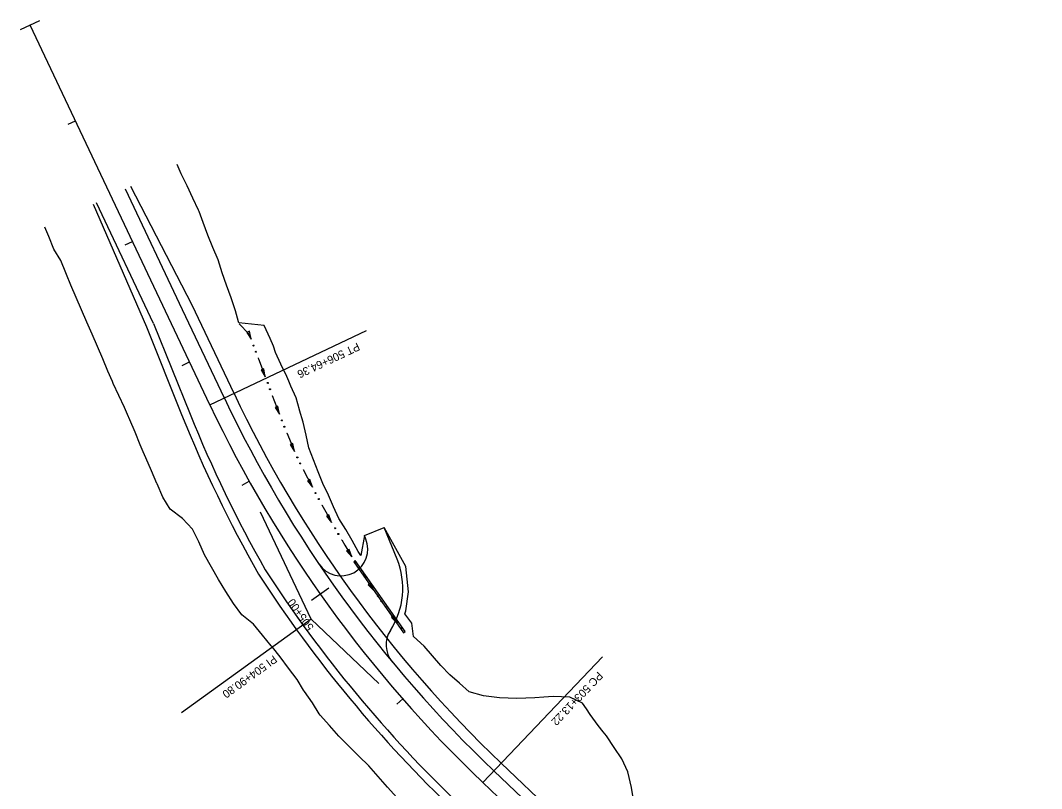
# Model space of a CAD drawing. Extents: x 948761 to 996004, y 1858548 to 1925175.
# Drawn here: x 955106 to 955872, y 1923318 to 1923894 of the extents above; entities that cross this region are included whole.
import ezdxf

# ---------------------------------------------------------------- set-up
doc = ezdxf.new("R2010")
doc.units = 0
for name, color, linetype in [('62', 7, 'Continuous'), ('R_Drainage', 7, 'Continuous'), ('R_Horz Alg', 7, 'Continuous'), ('R_Horz Alg Annot', 7, 'Continuous'), ('R_Proposed Const Limits', 7, 'Continuous'), ('R_Proposed Road', 7, 'Continuous')]:
    doc.layers.add(name, color=color, linetype=linetype)

msp = doc.modelspace()

# ---------------------------------------------------------------- linework, layer by layer
at = {"layer": '62'}
for p, q in [((955278.24, 1923660.85), (955276.27, 1923660.09)), ((955276.27, 1923660.09), (955279.43, 1923654.88)), ((955279.43, 1923654.88), (955278.24, 1923660.85)), ((955289.02, 1923632.8), (955287.04, 1923632.06)), ((955287.04, 1923632.06), (955290.12, 1923626.81)), ((955290.12, 1923626.81), (955289.02, 1923632.8)), ((955299.47, 1923604.65), (955297.49, 1923603.89)), ((955297.49, 1923603.89), (955300.65, 1923598.68)), ((955300.65, 1923598.68), (955299.47, 1923604.65)), ((955310.63, 1923576.81), (955308.68, 1923575.98)), ((955312.01, 1923570.87), (955310.63, 1923576.81)), ((955308.68, 1923575.98), (955312.01, 1923570.87)), ((955323.61, 1923549.82), (955321.73, 1923548.84)), ((955321.73, 1923548.84), (955325.45, 1923544.02)), ((955325.45, 1923544.02), (955323.61, 1923549.82)), ((955337.86, 1923523.42), (955336.02, 1923522.39)), ((955339.86, 1923517.66), (955337.86, 1923523.42)), ((955336.02, 1923522.39), (955339.86, 1923517.66)), ((955352.87, 1923497.44), (955351.05, 1923496.35)), ((955351.05, 1923496.35), (955355.05, 1923491.75)), ((955355.05, 1923491.75), (955352.87, 1923497.44)), ((955368.99, 1923472.18), (955367.25, 1923470.98)), ((955367.25, 1923470.98), (955371.51, 1923466.63)), ((955371.51, 1923466.63), (955368.99, 1923472.18)), ((955386.33, 1923447.7), (955384.63, 1923446.44)), ((955389.05, 1923442.24), (955386.33, 1923447.7)), ((955384.63, 1923446.44), (955389.05, 1923442.24))]:
    msp.add_line(p, q, dxfattribs=at)
for points in [[(955270.43, 1923666.56), (955277.83, 1923659), (955279.43, 1923654.88)], [(955284.86, 1923640.9), (955284.87, 1923640.86)], [(955284.87, 1923640.86), (955285.08, 1923640.31), (955288.59, 1923630.91), (955290.12, 1923626.81)], [(955295.3, 1923612.73), (955295.31, 1923612.71), (955295.32, 1923612.7)], [(955295.32, 1923612.7), (955298.69, 1923603.74), (955300.65, 1923598.68)], [(955306.2, 1923584.74), (955306.22, 1923584.71)], [(955306.22, 1923584.71), (955309.4, 1923577), (955312.01, 1923570.87)], [(955318.55, 1923557.38), (955318.56, 1923557.34)], [(955318.56, 1923557.34), (955321.8, 1923551), (955325.45, 1923544.02)], [(955332.57, 1923530.81), (955332.58, 1923530.78)], [(955332.58, 1923530.78), (955335.44, 1923525.59), (955339.86, 1923517.66)], [(955347.35, 1923504.67), (955347.37, 1923504.63)], [(955347.37, 1923504.63), (955349.79, 1923500.52), (955354.75, 1923492.25), (955355.05, 1923491.75)], [(955363.07, 1923479.08), (955363.09, 1923479.05)], [(955363.09, 1923479.05), (955365.12, 1923475.98), (955365.77, 1923475.01), (955370.56, 1923468.02), (955371.52, 1923466.64)], [(955380.18, 1923454.39), (955380.2, 1923454.36)], [(955380.2, 1923454.36), (955381.7, 1923452.27), (955386.83, 1923445.25), (955387.4, 1923444.47), (955389.11, 1923442.29)]]:
    msp.add_lwpolyline(points, dxfattribs=at)
for centre in [(955281.27, 1923650.22), (955283.09, 1923645.55), (955291.9, 1923622.13), (955293.62, 1923617.43), (955302.51, 1923594.03), (955304.37, 1923589.38), (955314.11, 1923566.33), (955316.34, 1923561.84), (955327.84, 1923539.62), (955330.21, 1923535.2), (955342.38, 1923513.33), (955344.86, 1923508.99), (955357.71, 1923487.51), (955360.36, 1923483.26), (955374.42, 1923462.56), (955377.31, 1923458.47), (955392.22, 1923438.37)]:
    msp.add_circle(centre, 0.375, dxfattribs=at)
at = {"layer": 'R_Drainage'}
for p, q in [((955357.6, 1923489.04), (955356.37, 1923488.18)), ((955356.37, 1923488.18), (955393.75, 1923435)), ((955394.98, 1923435.87), (955357.6, 1923489.04)), ((955393.75, 1923435), (955394.98, 1923435.87))]:
    msp.add_line(p, q, dxfattribs=at)
at = {"layer": 'R_Horz Alg'}
for p, q in [((955248.56, 1923605.7), (955113.72, 1923890.38)), ((955858.37, 1922937.15), (955453.2, 1923322.8))]:
    msp.add_line(p, q, dxfattribs=at)
msp.add_arc((956111.57, 1924014.49), 954.93, 205.34627, 226.41419, dxfattribs=at)
at = {"layer": 'R_Horz Alg Annot'}
for q in [(955286.57, 1923525.46), (955375.23, 1923397.01)]:
    msp.add_line((955324.58, 1923445.22), q, dxfattribs=at)
for points in [[(955106.49, 1923886.95), (955120.94, 1923893.8)], [(955106.49, 1923886.95), (955120.94, 1923893.8)], [(955142.26, 1923816.09), (955147.69, 1923818.66)], [(955185.07, 1923725.72), (955190.5, 1923728.28)], [(955248.56, 1923605.7), (955366.05, 1923661.35)], [(955227.88, 1923635.34), (955233.3, 1923637.91)], [(955272.81, 1923545.58), (955278.05, 1923548.51)], [(955324.79, 1923459.32), (955337.86, 1923468.55)], [(955324.58, 1923445.22), (955227.35, 1923374.89)], [(955453.2, 1923322.8), (955542.83, 1923416.96)], [(955388.64, 1923381.44), (955393.15, 1923385.39)]]:
    msp.add_lwpolyline(points, dxfattribs=at)
at = {"layer": 'R_Proposed Const Limits'}
for points in [[(955270.22, 1923667.28), (955270.02, 1923668), (955267.63, 1923676.3), (955264.38, 1923685.83), (955261.07, 1923695.32), (955257.7, 1923704.79), (955254.7, 1923714.44), (955250.65, 1923723.58), (955247.05, 1923732.94), (955243.45, 1923742.3), (955240.43, 1923750.61), (955240.02, 1923751.74), (955235.65, 1923760.74), (955231.42, 1923769.8), (955227.1, 1923778.82), (955223.91, 1923785.77)], [(955388.84, 1923311.48), (955381.66, 1923319.22), (955374.76, 1923327.22), (955367.85, 1923335.2), (955360.27, 1923342.58), (955352.78, 1923350.05), (955345.32, 1923357.56), (955338.33, 1923365.5), (955331.21, 1923373.33), (955330.47, 1923374.16), (955325.57, 1923382.36), (955319.47, 1923391), (955318.85, 1923391.85), (955313.91, 1923400.04), (955307.51, 1923408.42), (955301.31, 1923416.95), (955295.4, 1923424.11), (955294.58, 1923425.1), (955287.89, 1923433.29), (955281.22, 1923441.51), (955272.58, 1923448.42), (955266.31, 1923456.99), (955260.4, 1923465.79), (955254.98, 1923474.91), (955249.82, 1923484.18), (955244.52, 1923493.36), (955240.16, 1923503.08), (955235.57, 1923512.65), (955228.03, 1923520.55), (955227.96, 1923520.62), (955218.67, 1923527.51), (955213.17, 1923536.65), (955208.96, 1923546.47), (955208.89, 1923546.71), (955204.75, 1923556.27), (955200.53, 1923566.06), (955198.54, 1923570.59), (955196.35, 1923575.84), (955192.42, 1923585.35), (955188.45, 1923594.53), (955186.76, 1923598.61), (955184.51, 1923603.73), (955180.27, 1923612.79), (955176.06, 1923621.86), (955175.46, 1923623.21), (955171.97, 1923630.99), (955168.22, 1923640.28), (955164.36, 1923649.52), (955160.3, 1923658.66), (955156.21, 1923667.78), (955152.25, 1923676.97), (955148.27, 1923686.15), (955144.33, 1923695.35), (955140.98, 1923703.5), (955140.53, 1923704.61), (955136.78, 1923713.9), (955131.59, 1923722.51), (955127.81, 1923731.79), (955124.7, 1923738.78), (955124.67, 1923738.85)], [(955364.39, 1923507.81), (955361.69, 1923492.9), (955359.85, 1923495.77), (955355.17, 1923504.15), (955350.43, 1923512.47), (955345.35, 1923520.56), (955341.31, 1923529.29), (955337.43, 1923538.1), (955333.36, 1923546.75), (955329.67, 1923555.61), (955326.3, 1923564.62), (955322.81, 1923573.53), (955322.79, 1923573.62), (955320.68, 1923583.15), (955318.49, 1923592.67), (955315.72, 1923601.83), (955315.65, 1923602.04), (955313.14, 1923610.92), (955309.33, 1923619.81), (955307.77, 1923623.44), (955306.2, 1923627.04), (955301.75, 1923636.23), (955297.82, 1923645.08), (955296.14, 1923649.81), (955293.87, 1923655.37), (955289.13, 1923665.25), (955270.22, 1923667.28)], [(955399.86, 1923442.11), (955394.74, 1923449.26), (955395.52, 1923451.46), (955397.58, 1923465.67), (955395.53, 1923484.54), (955379.21, 1923513.84)], [(955566.75, 1923306.88), (955564.56, 1923319.08), (955561.91, 1923330.8), (955557.33, 1923340.49), (955551.68, 1923349.06), (955546.03, 1923357.63), (955543.37, 1923360.63), (955539.6, 1923365.38), (955533.75, 1923373.74), (955530.89, 1923377.98), (955528.02, 1923382.22), (955518.49, 1923386.72), (955506.04, 1923387.28), (955499.06, 1923386.7), (955492.08, 1923386.12), (955478.6, 1923385.76), (955465.58, 1923386.13), (955453.68, 1923387.82), (955442.84, 1923390.73), (955435.66, 1923397.14), (955428.44, 1923403.54), (955421.72, 1923410.42), (955415.56, 1923417.78), (955409.12, 1923424.91), (955401.28, 1923432.2), (955400.42, 1923438.24), (955399.86, 1923442.11)]]:
    msp.add_lwpolyline(points, dxfattribs=at)
at = {"layer": 'R_Proposed Road'}
for p, q in [((955206.34, 1923666.8), (955163.52, 1923757.16)), ((955200.91, 1923664.22), (955227.38, 1923598.43)), ((955206.34, 1923666.8), (955233.74, 1923598.68)), ((955364.39, 1923507.81), (955379.21, 1923513.84)), ((955365.47, 1923505.17), (955364.39, 1923507.81)), ((955388.87, 1923490.12), (955379.21, 1923513.84)), ((955872.16, 1922951.64), (955466.99, 1923337.28)), ((955866.65, 1922945.84), (955461.47, 1923331.49))]:
    msp.add_line(p, q, dxfattribs=at)
for points in [[(955266.64, 1923614.26), (955235.26, 1923680.49), (955189.27, 1923769.36)], [(955259.41, 1923610.84), (955228.03, 1923677.07), (955185.21, 1923767.43)], [(955161.12, 1923756.03), (955200.91, 1923664.22)]]:
    msp.add_lwpolyline(points, dxfattribs=at)
for centre, radius, start, end in [((956111.57, 1924014.49), 942.93, 205.34627, 226.41419), ((956111.57, 1924014.49), 934.93, 205.34627, 226.41419), ((956136.48, 1923962.96), 979.46, 201.84984, 209.61457), ((956136.48, 1923962.96), 973.46, 201.97549, 209.60432), ((955346.94, 1923497.63), 20, 214.05765, 22.16364), ((955335.16, 1923468.24), 58, 327.13216, 22.16364), ((956111.57, 1924014.49), 984.93, 212.93877, 226.41419), ((956111.57, 1924014.49), 978.93, 212.94896, 226.41419), ((955400.67, 1923425.91), 20, 147.13216, 219.62285)]:
    msp.add_arc(centre, radius, start, end, dxfattribs=at)

# ---------------------------------------------------------------- texts
at = {"layer": 'R_Horz Alg'}
for rotation, p in [(115.34627, (955114.17, 1923890.59)), (115.34627, (955249.01, 1923605.91)), (128.14769, (955362.26, 1923425.95)), (136.41419, (955453.55, 1923323.16))]:
    msp.add_text('+', height=1, rotation=rotation, dxfattribs=at).set_placement(p)
at = {"layer": 'R_Horz Alg Annot'}
for s, rotation, p in [('PT 506+64.36', 205.34627, (955359.15, 1923652.55)), ('505+00', 125.20769, (955326.79, 1923439.14)), ('PI 504+90.80', 215.88023, (955296.14, 1923418.48)), ('PC 503+13.22', 226.41419, (955539.56, 1923406.27))]:
    msp.add_text(s, height=6, rotation=rotation, dxfattribs=at).set_placement(p)

doc.saveas('drawing.dxf')
